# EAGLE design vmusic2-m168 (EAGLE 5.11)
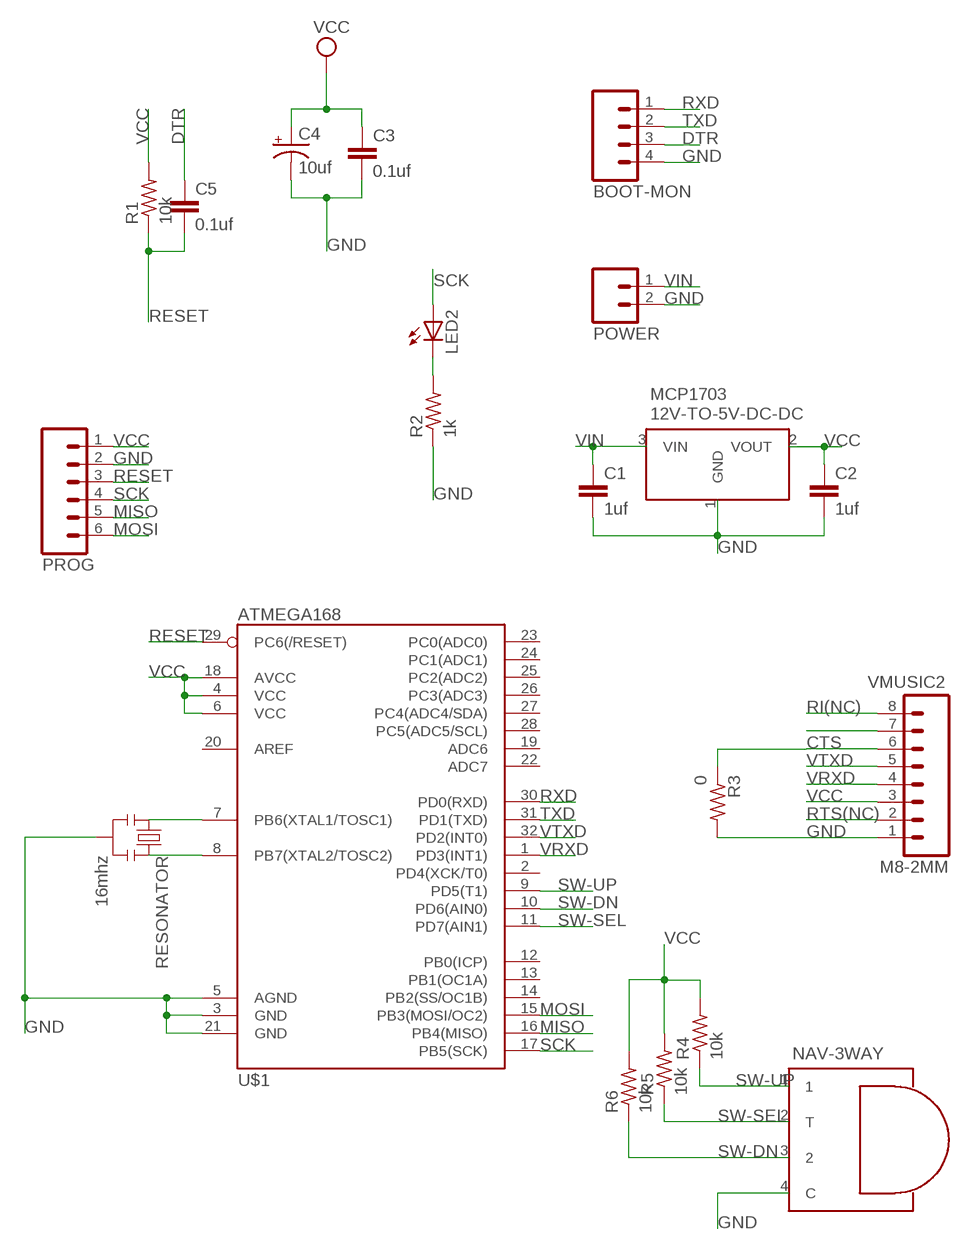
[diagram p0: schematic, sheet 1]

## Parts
12V-TO-5V-DC-DC  MCP1703  [SOT23-3]
BOOT-MON  M04PTH  [1X04]
C1  1uf  C-EUC1206  [C1206]
C2  1uf  C-EUC1206  [C1206]
C3  0.1uf  C-EUC0805  [C0805]
C4  10uf  CPOL-USUD-5X5,8  [UD-5X5,8_NICHICON]
C5  0.1uf  C-EUC0805  [C0805]
LED2  LEDCHIPLED_0805  [CHIPLED_0805]
NAV-3WAY  SWITCH-SFE-NAVIGATION-3WAY  [SIL4]
POWER  M02POLAR  [MOLEX-1X2]
PROG  M06SIP  [1X06]
R1  10k  R-US_R0805  [R0805]
R2  1k  R-US_R1210  [R1210]
R3  0  R-US_R1206  [R1206]
R4  10k  R-US_R0805  [R0805]
R5  10k  R-US_R0805  [R0805]
R6  10k  R-US_R0805  [R0805]
RESONATOR  16mhz  RESONATORSMD  [RESONATOR-SMD]
U$1  ATMEGA168  [TQFP32-08]
VMUSIC2  M8-2MM  [M8-2MM]

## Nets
CTS: R3.1 VMUSIC2.6
DTR: BOOT-MON.3 C5.1
GND: 12V-TO-5V-DC-DC.1(GND) BOOT-MON.4 C1.2 C2.2 C3.2 C4.- NAV-3WAY.4(C) POWER.2 PROG.2 R2.1 R3.2 RESONATOR.2 U$1.3(GND) U$1.5(AGND) U$1.21(GND) VMUSIC2.1
MISO: PROG.5 U$1.16(PB4(MISO))
MOSI: PROG.6 U$1.15(PB3(MOSI/OC2))
N$4: LED2.C R2.2
N$5: RESONATOR.3 U$1.8(PB7(XTAL2/TOSC2))
N$6: RESONATOR.1 U$1.7(PB6(XTAL1/TOSC1))
N$9: VMUSIC2.7
RESET: C5.2 PROG.3 R1.1 U$1.29(PC6(/RESET))
RI(NC): VMUSIC2.8
RTS(NC): VMUSIC2.2
RXD: BOOT-MON.1 U$1.30(PD0(RXD))
SCK: LED2.A PROG.4 U$1.17(PB5(SCK))
SW-DN: NAV-3WAY.3 R6.1 U$1.10(PD6(AIN0))
SW-SEL: NAV-3WAY.2(T) R5.1 U$1.11(PD7(AIN1))
SW-UP: NAV-3WAY.1 R4.1 U$1.9(PD5(T1))
TXD: BOOT-MON.2 U$1.31(PD1(TXD))
VCC: 12V-TO-5V-DC-DC.2(VOUT) C2.1 C3.1 C4.+ PROG.1 R1.2 R4.2 R5.2 R6.2 U$1.4(VCC) U$1.6(VCC) U$1.18(AVCC) VMUSIC2.3
VIN: 12V-TO-5V-DC-DC.3(VIN) C1.1 POWER.1
VRXD: U$1.1(PD3(INT1)) VMUSIC2.4
VTXD: U$1.32(PD2(INT0)) VMUSIC2.5
Unconnected: U$1.2(PD4(XCK/T0)) U$1.12(PB0(ICP)) U$1.13(PB1(OC1A)) U$1.14(PB2(SS/OC1B)) U$1.19(ADC6) U$1.20(AREF) U$1.22(ADC7) U$1.23(PC0(ADC0)) U$1.24(PC1(ADC1)) U$1.25(PC2(ADC2)) U$1.26(PC3(ADC3)) U$1.27(PC4(ADC4/SDA)) U$1.28(PC5(ADC5/SCL))

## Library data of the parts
12V-TO-5V-DC-DC = trl:MCP1703
BOOT-MON = SparkFun:M04: Header 4 Standard 4-pin 0.1" header. Use with straight break away headers (SKU : PRT-00116), right angle break away headers (PRT-00553), swiss pins (PRT-00743), machine pins (PRT-00117), and female headers (PRT-00115). Molex polarized connector foot print use with SKU : PRT-08231 with associated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
C1-C3 C5 = rcl:C-EU: CAPACITOR, European symbol
C4 = rcl:CPOL-US: POLARIZED CAPACITOR, American symbol
LED2 = led:LED: LED
NAV-3WAY = trl:SWITCH-SFE-NAVIGATION-3WAY
POWER = SparkFun:M02: Header 2
PROG = SparkFun:M06: Header 6 Standard 6-pin 0.1" header. Use with straight break away headers (SKU : PRT-00116), right angle break away headers (PRT-00553), swiss pins (PRT-00743), machine pins (PRT-00117), and female headers (PRT-00115). Molex polarized connector foot print use with SKU : PRT-08094 with associated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
R1-R6 = resistor:R-US_: RESISTOR, American symbol
RESONATOR = SparkFun:RESONATOR: Resonator Small SMD resonator. This is the itty bitty 10/20MHz resonators with built in caps. CSTCE10M0G55 and CSTCE20M0V53. Footprint has been reviewed closely but hasn't been tested yet.
U$1 = SparkFun:ATMEGA168
VMUSIC2 = trl:M8-2MM

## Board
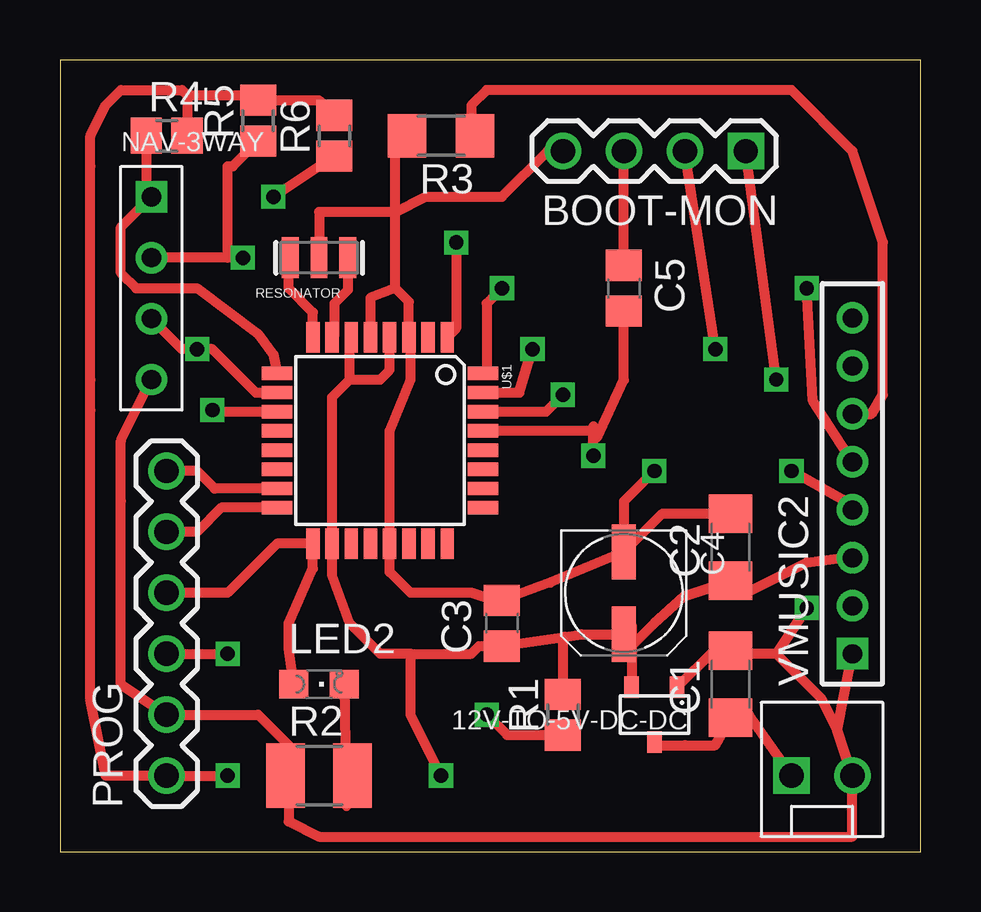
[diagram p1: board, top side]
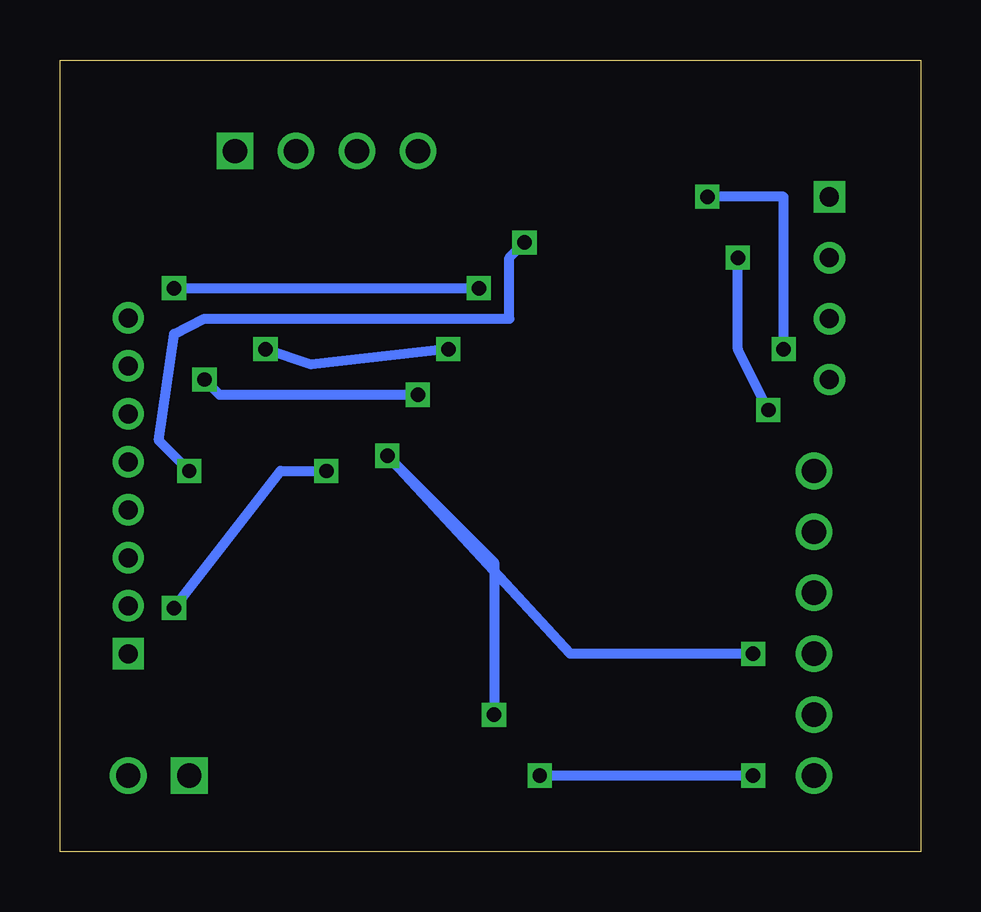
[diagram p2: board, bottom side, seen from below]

Size 35.87 x 33.01 mm. Coordinates in mm from the lower left corner, seen from the top.
Outline: 0,0 35.87,0 35.87,33.01 0,33.01 0,0
Copper layers (1*16): Top 0.035mm / dielectric 1.5mm / Bottom 0.035mm
Design rules "default": minimum track width 10mil, minimum drill 24mil, track to track 8mil, track to pad 8mil, pad to pad 8mil, via to via 8mil, smd to smd 8mil, copper to edge 40mil, drill to drill 8mil, minimum pad ring 10mil, minimum via ring 8mil, stop-mask expansion 4mil, vias tented up to drill 0mil, thermal gap 10mil

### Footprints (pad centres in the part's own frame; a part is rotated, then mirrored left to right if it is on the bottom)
SOT23-3 = smd 0.6 x 0.9: 1 -0.95,-1.15; 2 0.95,-1.15; 3 0,1.15
1X04 = drill 1.016 square: 1 0,0 | drill 1.016 round: 2 2.54,0; 3 5.08,0; 4 7.62,0
C1206 = smd 1.6 x 1.8: 1 -1.4,0; 2 1.4,0
C0805 = smd 1.3 x 1.5: 1 -0.95,0; 2 0.95,0
UD-5X5,8_NICHICON = smd 2.3 x 1: + 1.725,0; - -1.7,0
CHIPLED_0805 = smd 1.2 x 1.2: A 0,-1.05; C 0,1.05
SIL4 = drill 0.8 square: 1 0,3.81 | drill 0.8 round: 2 0,1.27; 3 0,-1.27; 4 0,-3.81
MOLEX-1X2 = drill 1.016 square: 1 0,0 | drill 1.016 round: 2 2.54,0
1X06 = drill 1.016 round: 1 0,0; 2 2.54,0; 3 5.08,0; 4 7.62,0; 5 10.16,0; 6 12.7,0
R0805 = smd 1.3 x 1.5: 1 -0.85,0; 2 0.85,0
R1210 = smd 1.6 x 2.7: 1 -1.4,0; 2 1.4,0
R1206 = smd 1.6 x 1.803: 1 -1.422,0; 2 1.422,0
RESONATOR-SMD = smd 0.7 x 1.7: 1 -1.2,0; 2 0,0; 3 1.2,0
TQFP32-08 = smd 1.27 x 0.559: 1 -4.293,2.8; 2 -4.293,2; 3 -4.293,1.2; 4 -4.293,0.4; 5 -4.293,-0.4; 6 -4.293,-1.2; 7 -4.293,-2; 8 -4.293,-2.8; 17 4.293,-2.8; 18 4.293,-2; 19 4.293,-1.2; 20 4.293,-0.4; 21 4.293,0.4; 22 4.293,1.2; 23 4.293,2; 24 4.293,2.8 | smd 0.559 x 1.27: 9 -2.8,-4.293; 10 -2,-4.293; 11 -1.2,-4.293; 12 -0.4,-4.293; 13 0.4,-4.293; 14 1.2,-4.293; 15 2,-4.293; 16 2.8,-4.293; 25 2.8,4.293; 26 2,4.293; 27 1.2,4.293; 28 0.4,4.293; 29 -0.4,4.293; 30 -1.2,4.293; 31 -2,4.293; 32 -2.8,4.293
M8-2MM = drill 0.8 square: 1 -6.35,0 | drill 0.8 round: 2 -4.35,0; 3 -2.35,0; 4 -0.35,0; 5 1.65,0; 6 3.65,0; 7 5.65,0; 8 7.65,0

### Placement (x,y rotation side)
12V-TO-5V-DC-DC  24.77,5.71 180 top
BOOT-MON  28.57,29.21 180 top
C1  27.94,6.99 90 top
C2  27.94,12.7 90 top
C3  18.41,9.53 90 top
C4  23.5,10.79 270 top
C5  23.5,23.5 270 top
LED2  10.79,6.99 270 top
NAV-3WAY  3.81,23.5 0 top
POWER  30.48,3.17 0 top
PROG  4.45,3.17 90 top
R1  20.95,5.71 90 top
R2  10.79,3.17 0 top
R3  15.88,29.84 180 top
R4  4.45,29.84 0 top
R5  8.26,30.48 90 top
R6  11.43,29.84 90 top
RESONATOR  10.79,24.77 180 top
U$1  13.34,17.14 270 top
VMUSIC2  33.02,14.61 90 top

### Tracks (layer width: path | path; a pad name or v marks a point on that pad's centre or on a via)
CTS
  Top 0.406: VMUSIC2.6 33.81,18.25 34.29,19.05 34.29,25.4 33.02,29.21 30.48,31.75 17.78,31.75 17.14,31.11 17.14,30 R3.1
DTR
  Top 0.406: C5.1 BOOT-MON.3
GND  (via drill 0.6)
  Top 0.406: C4.- 20.43,11.22 C3.2 18.09,10.47 17.14,10.79 14.61,10.79 13.73,11.66 U$1.21 13.73,17.55 14.61,19.68 14.61,21.37 U$1.3 14.54,22.93 13.97,23.5 | R2.1 9.39,4.58 8.26,5.71 | 10.79,26.67 RESONATOR.2 10.79,26.67 | U$1.5 12.94,23.09 13.97,23.5 | 10.79,26.67 12.06,26.67 13.97,26.67 | 13.97,23.5 13.97,26.67 | PROG.2 8.26,5.71 | PROG.2 8.26,5.71 | PROG.2 2.54,6.99 2.54,14.61 2.54,17.14 NAV-3WAY.4 | 13.97,29.84 R3.2 | POWER.2 32.38,5.08 | 32.38,5.08 VMUSIC2.1 | POWER.2 32.38,5.08 | 32.38,5.08 31.75,6.35 29.84,8.26 | 29.84,8.26 28.7,8.26 C1.2 27.23,8.38 12V-TO-5V-DC-DC.1 | BOOT-MON.4 20.32,29.21 18.41,27.3 15.24,27.3 13.97,26.67 | C2.2 25.1,14.1 C4.- | 8.26,5.71 9.53,4.45 9.53,1.27 10.79,0.64 33.02,0.64 POWER.2 | C4.- 23.5,14.61 v24.77,15.88 | 29.84,8.26 v31.11,10.16 | 13.97,26.67 13.97,29.84 | 14.76,29.84 14.61,29.84 13.97,29.84
  Bottom 0.406: v24.77,15.88 26.67,15.88 v31.11,10.16
MISO
  Top 0.406: U$1.16 6.72,14.35 5.71,13.34 PROG.5
MOSI
  Top 0.406: U$1.15 6.45,15.14 5.71,15.88 PROG.6
N$4
  Top 0.406: LED2.C 11.94,1.91 R2.2
N$5
  Top 0.406: U$1.8 10.54,22.48 9.53,23.5 9.53,24.7 RESONATOR.3
N$6
  Top 0.406: RESONATOR.1 11.99,23.43 11.43,22.86 11.43,21.53 U$1.7
RESET  (via drill 0.6)
  Top 0.406: 22.41,17.55 U$1.29 | 22.41,17.55 22.38,17.27 23.5,19.66 C5.2 | PROG.3 v6.99,8.26 | v22.23,16.51 22.23,17.73 22.41,17.55 | R1.1 18.63,4.87 v17.78,5.71
  Bottom 0.406: v6.99,8.26 14.61,8.26 v22.23,16.51 17.78,12.06 v17.78,5.71
RXD  (via drill 0.6)
  Top 0.406: U$1.30 20.25,18.34 v20.95,19.05 | v29.84,19.68 BOOT-MON.1
  Bottom 0.406: v20.95,19.05 29.21,19.05 v29.84,19.68
SCK
  Top 0.406: LED2.A 9.53,8.47 9.53,9.53 10.54,11.8 U$1.17 9.04,12.85 6.99,10.79 PROG.4
SW-DN  (via drill 0.6)
  Top 0.406: v8.89,27.3 R6.1 | U$1.10 8.16,19.14 7.62,19.68 6.99,20.32 6.35,20.95 v5.71,20.95 5.08,20.95 NAV-3WAY.3
  Bottom 0.406: v8.89,27.3 5.71,27.3 v5.71,20.95
SW-SEL  (via drill 0.6)
  Top 0.406: 6.99,24.77 NAV-3WAY.2 | 6.99,24.77 6.99,28.57 7.2,28.57 R5.1 | U$1.11 6.42,18.34 v6.35,18.41 | v7.62,24.77 6.99,24.77
  Bottom 0.406: v6.35,18.41 7.62,20.95 v7.62,24.77
SW-UP
  Top 0.406: U$1.9 8.89,20.73 8.26,21.59 5.71,23.5 3.17,23.5 2.54,24.13 2.54,26.04 NAV-3WAY.1 3.6,27.52 R4.1
TXD  (via drill 0.6)
  Top 0.406: U$1.31 19.14,19.14 v19.68,20.95 | v27.3,20.95 BOOT-MON.2
  Bottom 0.406: v19.68,20.95 25.4,20.32 v27.3,20.95
VCC  (via drill 0.6)
  Top 0.406: 21.04,8.97 C3.1 17.46,8.57 17.14,8.26 14.61,8.26 | 21.04,8.97 21.73,9.07 C4.+ 23.83,9.4 | 14.61,8.26 13.34,8.26 12.06,9.53 11.34,11.53 U$1.18 11.34,18.95 12.06,19.68 | 12.06,19.68 12.06,21.37 U$1.6 | U$1.4 13.73,20.09 13.34,19.68 12.06,19.68 | v6.99,3.17 PROG.1 3.17,3.17 2.54,3.17 1.91,3.17 1.27,6.35 1.27,18.41 1.27,19.68 1.27,28.57 1.27,29.84 1.91,31.11 2.54,31.75 5.08,31.75 5.29,31.54 | v15.88,3.17 14.61,5.71 14.61,8.26 | 23.83,9.4 12V-TO-5V-DC-DC.2 | 23.83,9.4 23.83,8.59 24.77,9.53 26.04,10.66 C2.1 28.45,10.79 28.57,10.79 31.11,12.06 32.58,12.26 VMUSIC2.3 | R1.2 20.95,8.88 21.04,8.97 | 5.29,31.54 R4.2 | 5.29,31.54 8.05,31.54 R5.2 10.79,31.33 R6.2
  Bottom 0.406: v6.99,3.17 v15.88,3.17
VIN
  Top 0.406: 12V-TO-5V-DC-DC.3 24.77,4.45 26.04,4.45 27.3,4.45 C1.1 28.7,5.71 POWER.1
VRXD  (via drill 0.6)
  Top 0.406: VMUSIC2.4 33.37,14.26 v30.48,15.88 | v16.51,25.4 16.51,21.81 U$1.1
  Bottom 0.406: v30.48,15.88 31.75,17.14 31.11,21.59 29.84,22.23 17.14,22.23 17.14,24.77 v16.51,25.4
VTXD  (via drill 0.6)
  Top 0.406: VMUSIC2.5 31.37,18.8 v31.11,23.5 | v18.41,23.5 17.78,22.86 17.78,20.1 U$1.32
  Bottom 0.406: v31.11,23.5 19.05,23.5 v18.41,23.5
